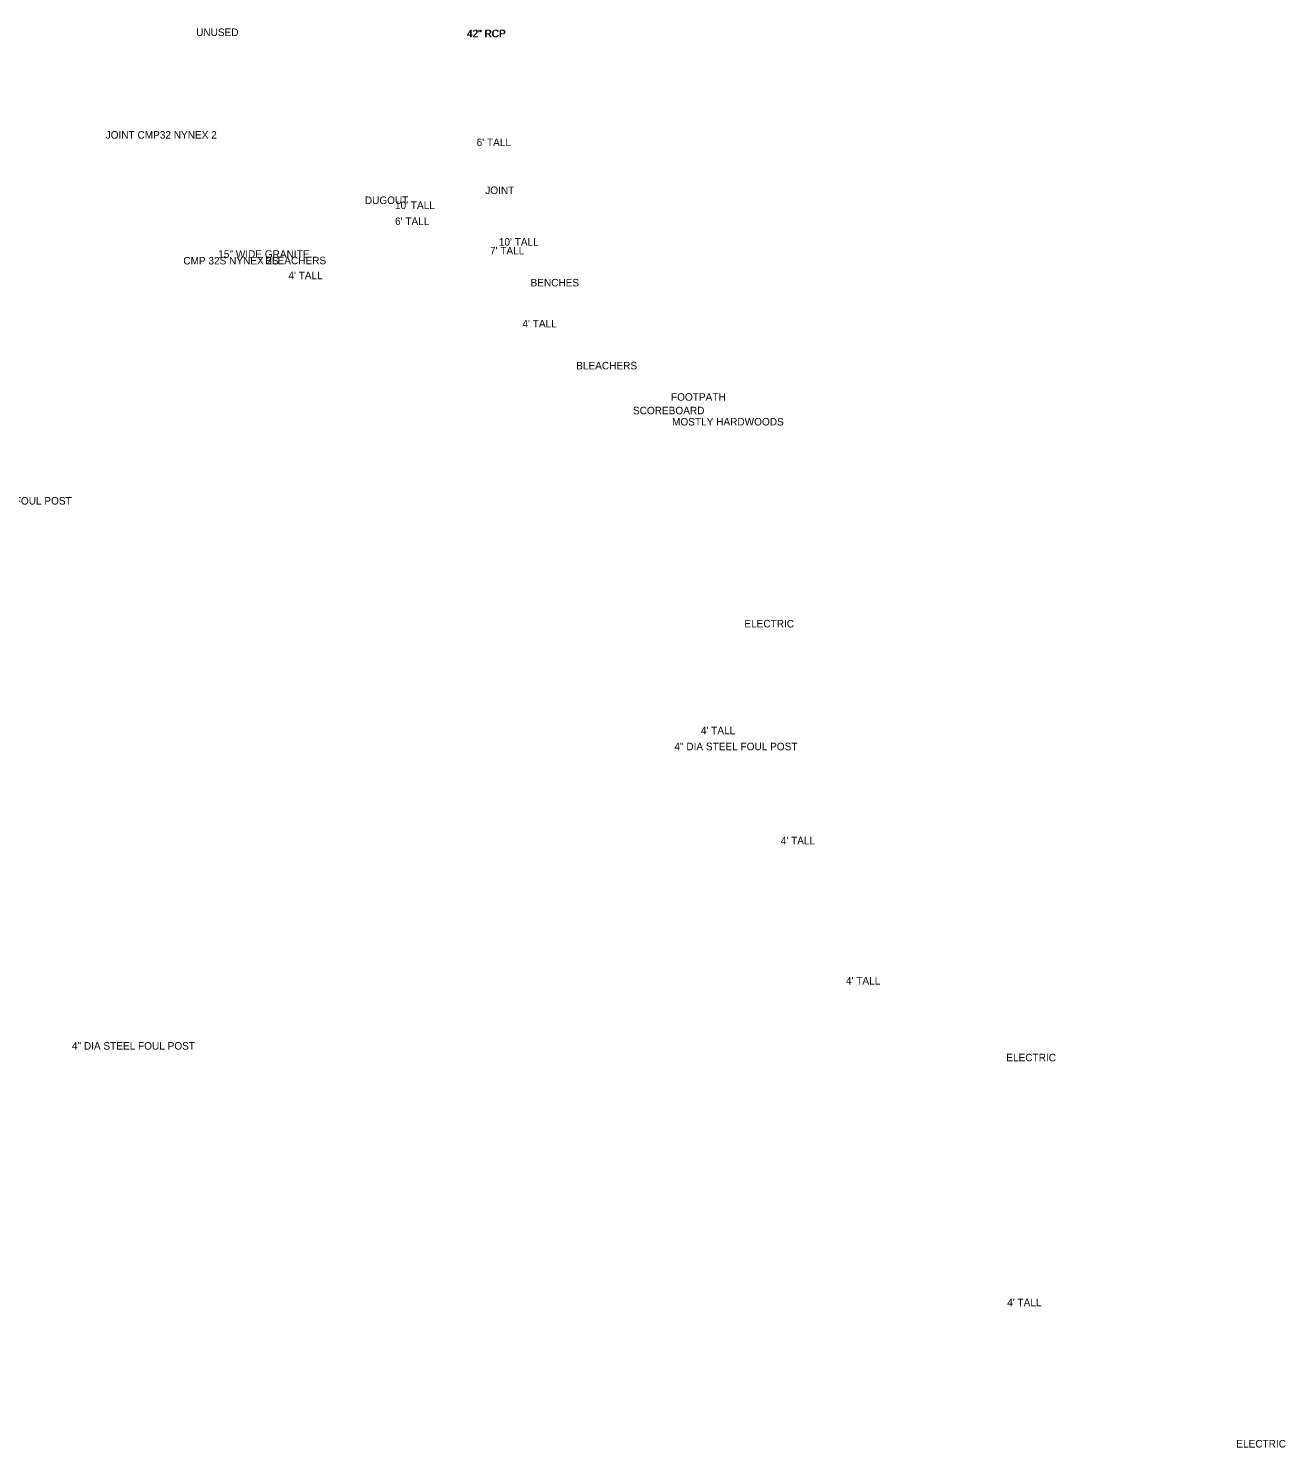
# Model space of a CAD drawing. Extents: x 939002 to 940105, y 627262 to 628202.
# Drawn here: x 939420.3 to 939838.5, y 627262.3 to 627734.3 of the extents above; entities that cross this region are included whole.
import ezdxf

# ---------------------------------------------------------------- set-up
doc = ezdxf.new("R2010")
doc.units = 0
for name, color, linetype in [('S_Annotation_Label', 7, 'Continuous'), ('S_Buildings', 7, 'Continuous'), ('S_Drainage_Culvert_Top', 7, 'Continuous'), ('S_Drainage_Invert', 7, 'Continuous'), ('S_Fencing_ChainLink', 7, 'Continuous'), ('S_Ground_Elevation', 7, 'Continuous'), ('S_RetWall_Top', 7, 'Continuous'), ('S_Roadway_Entr_Field_Wood', 7, 'Continuous'), ('S_Traffic_Post_Conc', 7, 'Continuous'), ('S_Traffic_Sign_DoublePost', 7, 'Continuous'), ('S_Trees_TreeLine', 7, 'Continuous'), ('S_Utilities_Pole_Power', 7, 'Continuous'), ('S_Utilities_Pole_Stub', 7, 'Continuous'), ('S_Utilities_Pole_Support3', 7, 'Continuous')]:
    doc.layers.add(name, color=color, linetype=linetype)

msp = doc.modelspace()

# ---------------------------------------------------------------- texts
at = {"layer": 'S_Annotation_Label'}
for s, p in [('BLEACHERS', (939499.09, 627655.85)), ('BENCHES', (939587.33, 627648.48)), ('BLEACHERS', (939602.53, 627620.89))]:
    msp.add_text(s, height=2.5, dxfattribs=at).set_placement(p)
at = {"layer": 'S_Buildings'}
msp.add_text('DUGOUT', height=2.5, dxfattribs=at).set_placement((939532.21, 627675.89))
at = {"layer": 'S_Drainage_Culvert_Top'}
msp.add_text('42" RCP', height=2.5, dxfattribs=at).set_placement((939566.09, 627731.29))
at = {"layer": 'S_Drainage_Invert'}
msp.add_text('42" RCP', height=2.5, dxfattribs=at).set_placement((939566.3, 627731.36))
at = {"layer": 'S_Fencing_ChainLink'}
for s, p in [("6' TALL", (939569.41, 627695.14)), ("10' TALL", (939542.24, 627674.22)), ("10' TALL", (939576.79, 627662.03)), ("4' TALL", (939644.01, 627499.57)), ("4' TALL", (939670.59, 627462.95)), ("4' TALL", (939692.27, 627416.34)), ("4' TALL", (939745.91, 627309.35))]:
    msp.add_text(s, height=2.5, dxfattribs=at).set_placement(p)
at = {"layer": 'S_Ground_Elevation'}
for s, p in [("6' TALL", (939542.26, 627668.9)), ("7' TALL", (939573.85, 627659.1)), ("4' TALL", (939506.79, 627650.85)), ("4' TALL", (939584.65, 627634.86))]:
    msp.add_text(s, height=2.5, dxfattribs=at).set_placement(p)
at = {"layer": 'S_RetWall_Top'}
msp.add_text('15" WIDE GRANITE', height=2.4999, dxfattribs=at).set_placement((939483.45, 627657.99))
at = {"layer": 'S_Roadway_Entr_Field_Wood'}
msp.add_text('FOOTPATH', height=2.5, dxfattribs=at).set_placement((939634.05, 627610.47))
at = {"layer": 'S_Traffic_Post_Conc'}
for p in [(939393.77, 627575.94), (939635.2, 627494.24), (939434.78, 627394.68)]:
    msp.add_text('4" DIA STEEL FOUL POST', height=2.4999, dxfattribs=at).set_placement(p)
at = {"layer": 'S_Traffic_Sign_DoublePost'}
msp.add_text('SCOREBOARD', height=2.5, dxfattribs=at).set_placement((939621.41, 627605.96))
at = {"layer": 'S_Trees_TreeLine'}
msp.add_text('MOSTLY HARDWOODS', height=2.4999, dxfattribs=at).set_placement((939634.42, 627602.24))
at = {"layer": 'S_Utilities_Pole_Power'}
for s, height, p in [('JOINT CMP32 NYNEX 2', 2.4999, (939446, 627697.62)), ('JOINT', 2.5, (939572.28, 627679.2)), ('ELECTRIC', 2.5, (939658.47, 627535.08)), ('ELECTRIC', 2.5, (939745.61, 627390.8)), ('ELECTRIC', 2.5, (939822.12, 627262.37))]:
    msp.add_text(s, height=height, dxfattribs=at).set_placement(p)
at = {"layer": 'S_Utilities_Pole_Stub'}
msp.add_text('UNUSED', height=2.5, dxfattribs=at).set_placement((939476.09, 627731.75))
at = {"layer": 'S_Utilities_Pole_Support3'}
msp.add_text('CMP 32S NYNEX 2S', height=2.4999, dxfattribs=at).set_placement((939471.83, 627655.79))

doc.saveas('drawing.dxf')
